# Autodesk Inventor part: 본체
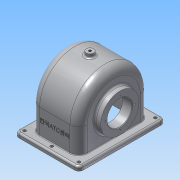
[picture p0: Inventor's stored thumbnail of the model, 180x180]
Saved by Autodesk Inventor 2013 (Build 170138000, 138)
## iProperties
Created: 2015-09
Part Number: 본체
Material: 알루미늄 6061
Document SubType Name: Modeling
Designer: semtle
Density: 2.71 g/cm^3
Mass: 690.142 g
Surface Area: 895.532 cm^2
Volume: 254.665 cm^3
Author: semtle
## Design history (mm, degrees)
sketch "스케치1"
  geometry: L1 (-52, 70)-(52, 70); L2 (52, 70)-(52, -70); L3 (52, -70)-(-52, -70); L4 (-52, -70)-(-52, 70); 1 further point
  constraints: 8 end point, 2 parallel, 1 horizontal, 1 perpendicular
  dimensions: "d0" = 140 distance between parallel lines of L3 L1; "d2" = 70 distance from line of point (0, 0) L1; "d3" = 104 distance between parallel lines of L2 L4; "d4" = 52 distance from line of point (0, 0) L4
extrude "돌출1" new body sketch "스케치1" distance "d5" = 7; taper "d6" = 0 deg
sketch "스케치2"
  geometry: 1 further point
sketch "스케치3"
  geometry: L1 (52, 7)-(-52, 7) reference; L2 (0, 47)-(0, 7); L3 (-52, 0)-(52, 0) reference; 1 further point
  constraints: 2 end point, 1 midpoint, 1 perpendicular
  dimensions: "d9" = 0 distance from line of point (0, 0) L2
sketch "스케치4"
  geometry: L1 (-70, 7)-(70, 7) reference; L2 (-70, 47)-(70, 47); L3 (70, 0)-(-70, 0) reference; L4 (0, 47)-(0, 0); L5 (-57, 47)-(-57, 7); L6 (57, 47)-(57, 7); A1 r 57 centre (0, 47) between (57, 47) and (-57, 47); 4 further points
  constraints: 8 end point, 8 point on line, 2 parallel, 2 perpendicular, 2 point on circle, 2 tangent, 1 centre point, 1 coincident, 1 midpoint
  dimensions: "d11" = 47 distance between parallel lines of L3 L2; "d18" = 57 radius of A1
extrude "돌출2" join sketch "스케치4" stored distance "d15" = 77; taper "d16" = 0 deg
fillet "모깎기1" dims "d19" = 14
fillet "모깎기2" dims "d20" = 7
sketch "스케치5"
  geometry: C1 r 31 at (-47, 0); A1 r 43 centre (-47, 0) between (-47, 43) and (-47, -43) reference; 1 further point
  constraints: 1 centre point, 1 coincident
  dimensions: "d21" = 62 diameter of C1
extrude "돌출3" join sketch "스케치5" distance "d23" = 10; taper "d24" = 0 deg
sketch "스케치6"
  geometry: C1 r 31 at (0, 0) reference; C2 r 20 at (0, 0); 1 further point
  constraints: 1 centre point, 1 coincident
  dimensions: "d25" = 40 diameter of C2
extrude "돌출4" cut sketch "스케치6" distance "d27" = 20; taper "d28" = 0 deg
node "작업 평면1"
node "작업 평면2"
sketch "스케치7"
  geometry: L1 (-14, 0)-(-14, 43) reference; L2 (-14, -40)-(-14, 0) reference; L3 (63, 43)-(63, 0) reference; L4 (63, 0)-(63, -40) reference; L5 (-14, 0)-(63, 0); L6 (0, 57)-(49, 57) reference; L7 (0, 0)-(-14, 0) reference; L8 (-14, 0)-(-14, 0) reference; L9 (0, 0)-(-14, 0) reference; L10 (0, 0)-(0, 0) reference; L11 (-14, -40)-(63, -40); L12 (58.385, 43)-(58.385, 0); L13 (58.385, 0)-(58.385, -35.385); L14 (58.385, -35.385)-(-9.385, -35.385); L15 (-9.385, -35.385)-(-9.385, 0); L16 (-9.385, 0)-(-9.385, 43); A1 r 14 centre (49, 43) between (63, 43) and (49, 57) reference; A2 r 14 centre (0, 43) between (0, 57) and (-14, 43) reference; A3 r 9.967 centre (49, 43) between (58.967, 43) and (49, 52.967); 1 further point
  constraints: 14 end point, 2 point on circle, 1 centre point, 1 parallel, 1 perpendicular, 4 other
  node "투영된 루프1"
sketch "스케치8"
  geometry: C1 r 33 at (47, 0); A1 r 43 centre (47, 0) between (47, -43) and (47, 43) reference; 1 further point
  constraints: 1 centre point, 1 coincident
  dimensions: "d29" = 66 diameter of C1
extrude "돌출5" cut sketch "스케치8" distance "d31" = 5; taper "d32" = 0 deg
sketch "스케치9"
  geometry: C1 r 33 at (0, 0) reference; C2 r 20 at (0, 0); 1 further point
  constraints: 1 centre point, 1 coincident
  dimensions: "d33" = 40 diameter of C2
extrude "돌출6" cut sketch "스케치9" distance "d36" = 16; taper "d37" = 0 deg
sketch "스케치10"
  geometry: L1 (38.5, 80)-(38.5, 14) reference; L2 (-48.5, 78)-(-48.5, 16) reference; L3 (38.5, 47)-(-48.5, 47); L4 (33.5, 27)-(17.5, 27) reference; L5 (-45, 7)-(45, 7) reference; L6 (17.5, 27)-(17.5, 15.895); L7 (33.5, 80)-(33.5, 14) reference; L8 (33.5, 14)-(33.5, 7); L9 (17.5, 15.895)-(33.5, 7); L10 (-28.5, 27)-(-28.5, 67) reference; 1 further point
  constraints: 8 end point, 2 midpoint, 2 perpendicular, 1 point on line
revolve "회전1" sketch "스케치10" stored, may be unused: angle "d38" = 90 deg
sketch "스케치11"
  geometry: L1 (57, 47)-(57, 7) reference; L2 (-57, 7)-(-57, 47) reference; L3 (63, 0)-(63, 7) reference; L4 (-63, 0)-(63, 0) reference; L5 (-63, 7)-(-63, 0) reference; L6 (63, 7)-(-63, 7) reference; L7 (-52, 7)-(-52, 47); L8 (52, 47)-(52, 7); A1 r 57 centre (0, 47) between (57, 47) and (-57, 47) reference; A2 r 52 centre (0, 47) between (52, 47) and (-52, 47); 1 further point
  constraints: 4 end point, 2 point on circle, 1 centre point, 2 other
  dimensions: "d39" = 5 radial gap between concentric circles of A2 A1
extrude "돌출7" cut sketch "스케치11" stored distance "d41" = 66; taper "d42" = 0 deg
fillet "모깎기3" dims "d43" = 9
sketch "스케치12"
  geometry: L1 (33.5, 80)-(33.5, 14) reference; L2 (-45, 7)-(45, 7) reference; L3 (33.5, 27)-(19.199, 27); L4 (19.199, 27)-(19.199, 19); L5 (19.199, 19)-(33.5, 7); L6 (33.5, 27)-(33.5, 7); L7 (-33, 27)-(-33, 67) reference; L8 (33.5, 47)-(-33, 47); 1 further point
  constraints: 10 end point, 2 midpoint, 2 point on line, 1 collinear, 1 parallel, 1 perpendicular
  dimensions: "d44" = 56 diameter of L4.end L8; "d46" = 50 deg angle of L5 L4; "d48" = 40 diameter of L3 L8
revolve "회전2" sketch "스케치12" stored, may be unused: angle "d49" = 90 deg
fillet "모깎기4" dims "d50" = 3
chamfer "모따기1" distance "d51" = 1; stored, may be unused: second distance "d52" = 2, angle "d53" = 45 deg
node "작업 평면3"
sketch "스케치13"
  geometry: C1 r 6 at (0, 0); 1 further point
  constraints: 1 centre point, 1 coincident
  dimensions: "d55" = 12 diameter of C1
extrude "돌출8" join sketch "스케치13" stored distance "d57" = 66; taper "d58" = 0 deg
sketch "스케치14"
  geometry: C1 r 6 at (0, 0) reference; C2 r 2.5 at (0, 0)
  constraints: 1 centre point, 1 coincident
  dimensions: "d59" = 5 diameter of C2
hole "구멍1" sketch "스케치14" at (0, 0) diameter "d61" = 4.134; stored, may be unused: countersink angle "d65" = 90 deg, drill point angle "d67" = 118 deg; dims "d62" = 6, "d63" = 4, "d64" = 2, "d66" = 8
fillet "모깎기5" dims "d68" = 3
fillet "모깎기6" dims "d69" = 1
sketch "스케치15"
  geometry: L1 (-0.387, -13.398)-(49.387, -13.398); L2 (49.387, -13.398)-(49.387, -20.602); L3 (49.387, -20.602)-(-0.387, -20.602); L4 (-0.387, -20.602)-(-0.387, -13.398); L5 (-0.387, -17)-(49.387, -17); L6 (24.5, -13.398)-(24.5, -20.602); L7 (-14, 0)-(-14, -39) reference; L8 (69.5, -47)-(-20.5, -47) reference; 1 further point
  constraints: 4 end point, 4 midpoint, 2 other
  dimensions: "d70" = 38.5 distance between parallel lines of L6 L7; "d71" = 30 distance between parallel lines of L5 L8
feature "엠보싱1" sketch "스케치15" dims "d11" = 47, "d18" = 57, "d72" = 0.5, "d73" = 0
sketch "스케치16"
  geometry: C1 r 2.5 at (-44, 62); C2 r 2.5 at (0, 62); C3 r 2.5 at (44, 62); C4 r 2.5 at (44, -62); C5 r 2.5 at (0, -62); C6 r 2.5 at (-44, -62); 1 further point
  constraints: 6 centre point, 5 equal radius
  dimensions: "d74" = 5 diameter of C1; "d76" = 0 horizontal distance of C6.centre C1.centre; "d77" = 124 distance of C6.centre C1.centre; "d78" = 62 vertical distance of point (0, 0) C1.centre; "d79" = 44 distance of C2.centre C1.centre; "d80" = 44 distance of C3.centre C2.centre; "d81" = 44 distance of C5.centre C6.centre; "d82" = 44 distance of C4.centre C5.centre; "d83" = 124 distance of C4.centre C3.centre; "d84" = 62 vertical distance of point (0, 0) C3.centre; "d85" = 124 distance of C5.centre C2.centre; "d86" = 62 distance of point (0, 0) C2.centre; "d87" = 44 horizontal distance of point (0, 0) C6.centre
extrude "돌출9" cut sketch "스케치16" stored distance "d88" = 66; taper "d89" = 0 deg
sketch "스케치17" dims "d90" = 56
  geometry: L1 (0, 0)-(28, 0); C1 r 21 at (0, 0) reference; C2 r 1.5 at (28, 0); 1 further point
  constraints: 2 coincident, 2 end point, 1 centre point, 1 horizontal, 1 horizontal alignment, 2 other
  dimensions: "d92" = 3 diameter of C2
hole "구멍2" sketch "스케치17" at (28, 0) diameter "d93" = 2.459; stored, may be unused: countersink angle "d97" = 90 deg, drill point angle "d99" = 118 deg; dims "d94" = 7, "d95" = 4, "d96" = 2, "d98" = 9
sketch "스케치18" dims "d103" = 48
  geometry: L1 (0, 0)-(-24, 0); C1 r 21 at (0, 0) reference; C2 r 1.5 at (-24, 0); 1 further point
  constraints: 2 coincident, 2 end point, 1 centre point, 1 horizontal, 1 horizontal alignment, 2 other
  dimensions: "d105" = 3 diameter of C2
hole "구멍3" sketch "스케치18" at (-24, 0) diameter "d106" = 2.459; stored, may be unused: countersink angle "d110" = 90 deg, drill point angle "d112" = 118 deg; dims "d107" = 6, "d108" = 4, "d109" = 2, "d111" = 8
fillet "모깎기7" dims "d116" = 0.5
fillet "모깎기8" dims "d117" = 3
node "솔리드1"
pattern_circular "원형 패턴1" dims angle "d101" = 360 deg
pattern_circular "원형 패턴2" dims angle "d114" = 360 deg
node "투영된 루프2"
other parameters: "d13" = 5, "d17" = 114, "d40" = 66
